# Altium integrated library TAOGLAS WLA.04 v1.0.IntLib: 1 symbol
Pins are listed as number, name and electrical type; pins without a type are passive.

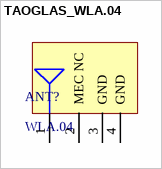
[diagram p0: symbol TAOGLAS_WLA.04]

## TAOGLAS_WLA.04
designator ANT?, comment WLA.04
2400MHz to 2500MHz Wi-Fi/Bluetooth/ WLAN/ZIGBEE/ISM Chip Antenna; ComponentLibStatus: Created; MFG: Taoglas; Temp_High: +85C; Temp_Low: -40C
footprint TAOGLAS_WLA.04 (2400MHz to 2500MHz Wi-Fi/Bluetooth/ WLAN/ZIGBEE/ISM Chip Antenna)
pins: 1 RF FEED, 2 MEC NC, 3 GND, 4 GND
